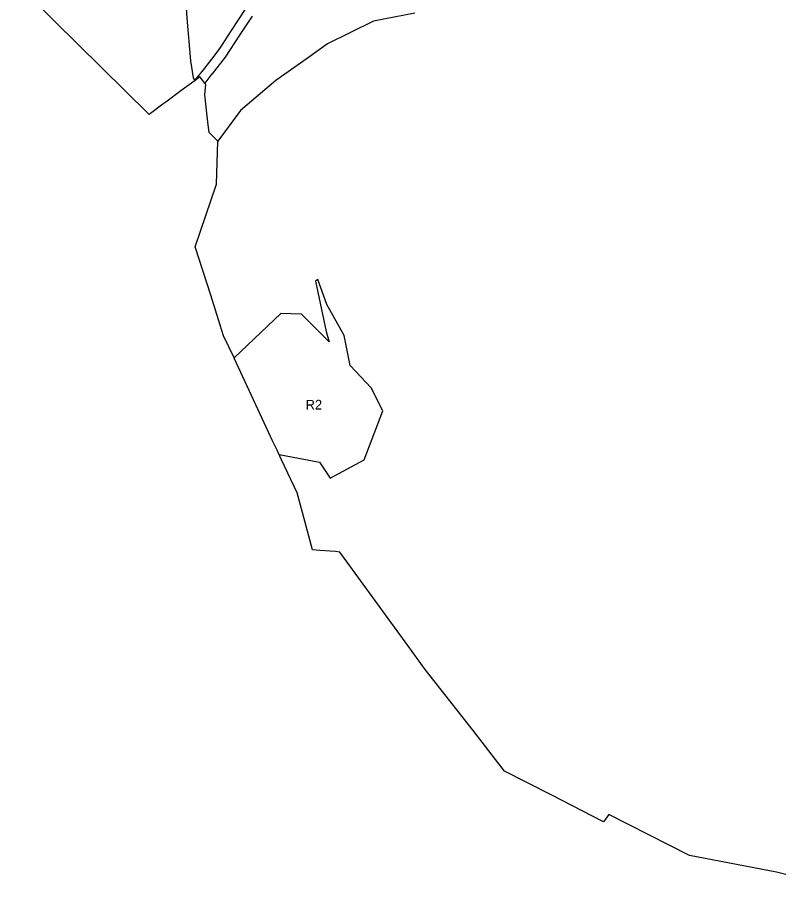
# Model space of a CAD drawing. Extents: x 7413438 to 7416393, y 5541665 to 5544118.
# Drawn here: x 7413580 to 7414051, y 5541671 to 5542209 of the extents above; entities that cross this region are included whole.
import ezdxf

# ---------------------------------------------------------------- set-up
doc = ezdxf.new("R2010")
doc.units = 0
doc.layers.add('linie_rozgraniczajace', color=7, linetype='Continuous')
doc.layers.add('oznaczenia_przeznaczen', color=7, linetype='Continuous')

msp = doc.modelspace()

# ---------------------------------------------------------------- linework, layer by layer
at = {"layer": 'linie_rozgraniczajace'}
for p, q in [((7413661.48, 5542148.73), (7413579.77, 5542229.31)), ((7413683.89, 5542223.9), (7413684.71, 5542208.4)), ((7413720.99, 5542214.05), (7413712.28, 5542200.78)), ((7413684.71, 5542208.4), (7413687.1, 5542182.02)), ((7413717.59, 5542197.95), (7413725.36, 5542209.76)), ((7413825.92, 5542211.63), (7413800.37, 5542206.67)), ((7413800.37, 5542206.67), (7413771.85, 5542192.47)), ((7413712.28, 5542200.78), (7413706.61, 5542192.17)), ((7413708.65, 5542184.36), (7413717.59, 5542197.95)), ((7413706.61, 5542192.17), (7413704.96, 5542189.64)), ((7413771.85, 5542192.47), (7413758.77, 5542183.1)), ((7413704.96, 5542189.64), (7413701.47, 5542184.91)), ((7413687.1, 5542182.02), (7413688.59, 5542171.48)), ((7413701.47, 5542184.91), (7413695.67, 5542177.47)), ((7413700.56, 5542173.99), (7413708.65, 5542184.36)), ((7413758.77, 5542183.1), (7413739.9, 5542169.83)), ((7413695.65, 5542177.45), (7413689.77, 5542169.91)), ((7413695.7, 5542177.45), (7413695.65, 5542177.45)), ((7413695.67, 5542177.47), (7413695.7, 5542177.45)), ((7413689.87, 5542169.78), (7413681.03, 5542163.3)), ((7413688.59, 5542171.48), (7413689.37, 5542170.45)), ((7413689.37, 5542170.45), (7413689.77, 5542169.91)), ((7413689.77, 5542169.91), (7413689.86, 5542169.8)), ((7413689.86, 5542169.8), (7413689.87, 5542169.78)), ((7413689.91, 5542169.8), (7413689.87, 5542169.78)), ((7413692.88, 5542171.98), (7413689.91, 5542169.8)), ((7413695.19, 5542169.01), (7413692.88, 5542171.98)), ((7413696.06, 5542168.2), (7413700.53, 5542173.95)), ((7413700.53, 5542173.95), (7413700.53, 5542174.01)), ((7413700.53, 5542174.01), (7413700.56, 5542173.99)), ((7413739.9, 5542169.83), (7413718.01, 5542151.15)), ((7413695.94, 5542168.04), (7413695.19, 5542169.01)), ((7413695.83, 5542160.97), (7413696.48, 5542167.34)), ((7413695.94, 5542168.04), (7413696.06, 5542168.2)), ((7413695.99, 5542167.97), (7413695.94, 5542168.04)), ((7413696.48, 5542167.34), (7413695.99, 5542167.97)), ((7413681.03, 5542163.3), (7413671.79, 5542156.41)), ((7413697.36, 5542147.68), (7413695.83, 5542160.97)), ((7413669.98, 5542155.06), (7413661.48, 5542148.73)), ((7413671.79, 5542156.41), (7413669.98, 5542155.06)), ((7413718.01, 5542151.15), (7413704.03, 5542132.26)), ((7413698.14, 5542140.65), (7413697.36, 5542147.68)), ((7413698.59, 5542137.48), (7413698.14, 5542140.65)), ((7413704.03, 5542132.26), (7413698.59, 5542137.48)), ((7413703.13, 5542105.59), (7413704.03, 5542132.26)), ((7413689.86, 5542066.63), (7413703.13, 5542105.59)), ((7413699.55, 5542036.71), (7413689.86, 5542066.63)), ((7413766, 5542046.47), (7413764.42, 5542045.38)), ((7413771.43, 5542031.02), (7413766, 5542046.47)), ((7413764.42, 5542045.38), (7413771.14, 5542014.35)), ((7413705.4, 5542018.26), (7413699.55, 5542036.71)), ((7413782.19, 5542011.74), (7413771.43, 5542031.02)), ((7413743, 5542025.44), (7413713.99, 5541997.91)), ((7413755.78, 5542024.95), (7413743, 5542025.44)), ((7413772.98, 5542007.93), (7413755.78, 5542024.95)), ((7413707.5, 5542011.62), (7413705.4, 5542018.26)), ((7413771.14, 5542014.35), (7413772.98, 5542007.93)), ((7413713.99, 5541997.91), (7413707.5, 5542011.62)), ((7413786, 5541993.17), (7413782.19, 5542011.74)), ((7413714.08, 5541997.72), (7413713.99, 5541997.91)), ((7413718.21, 5541988.9), (7413714.08, 5541997.72)), ((7413798.98, 5541979.36), (7413786, 5541993.17)), ((7413736.64, 5541949.2), (7413718.21, 5541988.9)), ((7413806.25, 5541965.13), (7413798.98, 5541979.36)), ((7413794.68, 5541934.66), (7413806.25, 5541965.13)), ((7413737.72, 5541946.88), (7413736.64, 5541949.2)), ((7413740.62, 5541940.73), (7413737.72, 5541946.88)), ((7413741.82, 5541938.17), (7413740.62, 5541940.73)), ((7413741.9, 5541938.02), (7413741.82, 5541938.17)), ((7413742.38, 5541937), (7413741.9, 5541938.02)), ((7413741.9, 5541938.02), (7413767, 5541933.28)), ((7413742.41, 5541936.94), (7413742.38, 5541937)), ((7413743.47, 5541934.7), (7413742.41, 5541936.94)), ((7413753.01, 5541914.29), (7413743.47, 5541934.7)), ((7413767, 5541933.28), (7413773.55, 5541923.29)), ((7413773.55, 5541923.29), (7413794.68, 5541934.66)), ((7413757.8, 5541896.79), (7413753.01, 5541914.29)), ((7413762.68, 5541878.97), (7413757.8, 5541896.79)), ((7413764.81, 5541878.82), (7413762.68, 5541878.97)), ((7413767.22, 5541878.63), (7413764.81, 5541878.82)), ((7413773.49, 5541878.14), (7413767.22, 5541878.63)), ((7413776.96, 5541877.87), (7413773.49, 5541878.14)), ((7413779.45, 5541877.59), (7413776.96, 5541877.87)), ((7413785.68, 5541869.04), (7413779.45, 5541877.59)), ((7413821.6, 5541819.73), (7413785.68, 5541869.04)), ((7413832.35, 5541804.79), (7413821.6, 5541819.73)), ((7413862.05, 5541767.07), (7413832.35, 5541804.79)), ((7413881.55, 5541741.82), (7413862.05, 5541767.07)), ((7413910.43, 5541727.09), (7413881.55, 5541741.82)), ((7413942.79, 5541710.35), (7413910.43, 5541727.09)), ((7413946.17, 5541714.91), (7413942.79, 5541710.35)), ((7413996.22, 5541689.6), (7413946.17, 5541714.91)), ((7414049.96, 5541679.14), (7413996.22, 5541689.6)), ((7414080.62, 5541671.45), (7414049.96, 5541679.14))]:
    msp.add_line(p, q, dxfattribs=at)

# ---------------------------------------------------------------- texts
at = {"layer": 'oznaczenia_przeznaczen'}
msp.add_text('R2', height=6, dxfattribs=at).set_placement((7413758.32, 5541965.89))

doc.saveas('drawing.dxf')
